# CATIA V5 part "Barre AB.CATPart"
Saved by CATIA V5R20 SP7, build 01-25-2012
Part number: Barre AB
Bounding box of the stored display mesh (mm): x -2 to 2, y -2.986 to 15.652, z -2.991 to 21.419
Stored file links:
  U:\IAO_bon\Barre AB.CATPart
  U:\IAO_bon\Cqueguiner_IAo.CATProduct
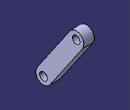
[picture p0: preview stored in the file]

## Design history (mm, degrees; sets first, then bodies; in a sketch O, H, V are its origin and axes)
Set1
  Point1 "Point B/G": linked copy from another document
  Point2 "Point A": linked copy from another document
Body1 (main body)
  Sketch1 on yz-plane, origin (0, 0, 0), H (0, 1, 0), V (0, 0, 1)
    line L1 (-2.4724, 1.6993) -> (10.1931, 20.1271)
    point P2 (10.1931, 20.1271)
    arc A1 centre (12.6655, 18.4278) radius 3 from (10.1931, 20.1271) to (15.1378, 16.7286) cw
    point P3 (12.6655, 18.4278)
    point P4 (15.1378, 16.7286)
    line L2 (15.1378, 16.7286) -> (2.4724, -1.6993)
    arc A2 centre (0, 0) radius 3 from (2.4724, -1.6993) to (-2.4724, 1.6993) cw
    point P6 (0, 0)
    reference projected point E1 (12.6655, 18.4278) from Point1
    reference projected point E2 (0, 0) from Point2
    circle A3 centre (12.6655, 18.4278) radius 1.5
    circle A4 centre (0, 0) radius 1.5
    distance P4 P2 = 6 (reference)
    radius A2 = 3
    angle L2 L1 = 0
    radius A1 = 3
    radius A3 = 1.5
    radius A4 = 1.5
    tangency: A1 L1, A2 L1, A2 L2
    coincidence: P3 E1, P6 E2
  Pad1: profile Sketch1, direction (1, 0, 0), length 2, opposite side length 2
